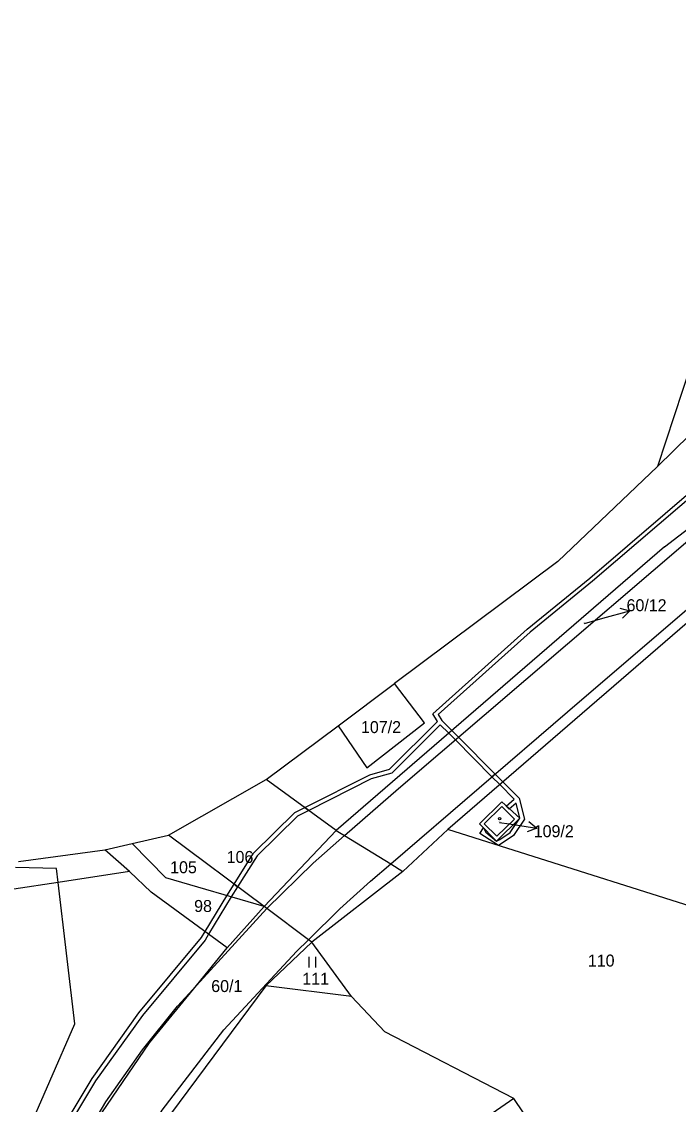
# Model space of a CAD drawing. Extents: x -670359 to -668019, y -978807 to -976674.
# Drawn here: x -670157 to -670063.7, y -977284.7 to -977130.8 of the extents above; entities that cross this region are included whole.
import ezdxf

# ---------------------------------------------------------------- set-up
doc = ezdxf.new("R2010")
doc.units = 0
for name, color, linetype in [('Hranice kat_území', 7, 'Continuous'), ('Hranice parcel', 7, 'Continuous'), ('Parcelní čísla', 7, 'Continuous'), ('Vnitřní kresba', 7, 'Continuous'), ('Věcná břemena k části', 7, 'Continuous'), ('Značky budov', 7, 'Continuous'), ('Značky kultur', 7, 'Continuous')]:
    doc.layers.add(name, color=color, linetype=linetype)

msp = doc.modelspace()

# ---------------------------------------------------------------- linework, layer by layer
at = {"layer": 'Hranice kat_území'}
for points in [[(-670061.94, -977179.61), (-670066.67, -977194.02)], [(-670080.85, -977207.52), (-670066.67, -977194.02)], [(-670080.85, -977207.52), (-670104.05, -977224.88)], [(-670112.07, -977230.89), (-670104.05, -977224.88)], [(-670122.28, -977238.53), (-670112.07, -977230.89)], [(-670136.18, -977246.45), (-670122.28, -977238.53)], [(-670141.33, -977247.61), (-670136.18, -977246.45)], [(-670157.5, -977250.17), (-670145.24, -977248.5)], [(-670145.24, -977248.5), (-670141.33, -977247.61)]]:
    msp.add_lwpolyline(points, dxfattribs=at)
at = {"layer": 'Hranice parcel'}
for p, q in [((-670091.98, -977244.8), (-670088.78, -977241.68)), ((-670088.78, -977241.68), (-670086.24, -977244.04)), ((-670089.55, -977247.29), (-670091.98, -977244.8)), ((-670086.24, -977244.04), (-670089.55, -977247.29))]:
    msp.add_line(p, q, dxfattribs=at)
for points in [[(-670104.59, -977250.52), (-670079.48, -977228.88), (-670031.98, -977188.17), (-670021.47, -977179.22), (-669995.68, -977157.04), (-669989.1, -977151.37), (-669968.95, -977134.02), (-669965.11, -977130.8)], [(-670025, -977183.9), (-670096.49, -977245.64)], [(-670057.51, -977185.02), (-670066.67, -977194.02)], [(-670111.14, -977246.5), (-670103.49, -977239.81), (-670043.26, -977188.26)], [(-670065.71, -977205.46), (-670043.26, -977188.26)], [(-670065.71, -977205.46), (-670112.33, -977245.77)], [(-670099.8, -977230.46), (-670104.05, -977224.88)], [(-670112.07, -977230.89), (-670108.01, -977236.86)], [(-670108.01, -977236.86), (-670099.8, -977230.46)], [(-670112.33, -977245.77), (-670122.28, -977238.53)], [(-670122.59, -977256.59), (-670136.18, -977246.45)], [(-670122.59, -977256.59), (-670112.33, -977245.77)], [(-670122.22, -977256.86), (-670115.62, -977250.42), (-670111.14, -977246.5)], [(-670096.49, -977245.64), (-670102.85, -977251.59)], [(-670050.66, -977260.11), (-670096.49, -977245.64)], [(-670141.7, -977251.6), (-670145.24, -977248.5)], [(-670136.55, -977252.48), (-670141.33, -977247.61)], [(-670141.7, -977251.6), (-670151.87, -977253.14)], [(-670138.64, -977254.54), (-670141.7, -977251.6)], [(-670116.3, -977261.29), (-670111.81, -977256.89), (-670107.46, -977252.99), (-670104.59, -977250.52)], [(-670102.85, -977251.59), (-670115.81, -977261.66)], [(-670151.87, -977253.14), (-670158.17, -977254.09)], [(-670122.59, -977256.59), (-670136.55, -977252.48)], [(-670127.82, -977262.45), (-670138.64, -977254.54)], [(-670132.18, -977267.78), (-670122.22, -977256.86)], [(-670127.82, -977262.45), (-670122.59, -977256.59)], [(-670206.03, -977490.9), (-670201.37, -977472.26), (-670196.78, -977453.99), (-670188.6, -977424.41), (-670168.29, -977357.64), (-670162.97, -977342.22), (-670144.87, -977298.55), (-670137.06, -977285.54), (-670128.3, -977274.09), (-670118, -977262.95), (-670116.3, -977261.29)], [(-670132.18, -977267.78), (-670127.82, -977262.45)], [(-670115.81, -977261.66), (-670122.33, -977267.85)], [(-670110.18, -977269.38), (-670115.81, -977261.66)], [(-670155.78, -977304.6), (-670149.86, -977292.46), (-670145.08, -977284.34), (-670139.87, -977276.96), (-670134.89, -977270.75), (-670132.18, -977267.78)], [(-670138.88, -977275.97), (-670132.18, -977267.78)], [(-670122.33, -977267.85), (-670138.33, -977289.41)], [(-670110.18, -977269.38), (-670122.33, -977267.85)], [(-670105.42, -977274.37), (-670110.18, -977269.38)], [(-670087.08, -977283.85), (-670105.42, -977274.37)], [(-670145.67, -977285.92), (-670138.88, -977275.97)], [(-670087.08, -977283.85), (-670131.79, -977314.81)], [(-670084.43, -977287.79), (-670087.08, -977283.85)]]:
    msp.add_lwpolyline(points, dxfattribs=at)
at = {"layer": 'Parcelní čísla'}
for p, q in [((-670072.05, -977214.16), (-670070.6, -977214.54)), ((-670077.05, -977216.33), (-670074.45, -977215.61)), ((-670089.12, -977244.63), (-670087.77, -977244.83)), ((-670084.99, -977244.5), (-670083.82, -977245.44))]:
    msp.add_line(p, q, dxfattribs=at)
for points in [[(-670074.45, -977215.61), (-670070.6, -977214.54), (-670071.65, -977215.61)], [(-670087.77, -977244.83), (-670083.82, -977245.44), (-670085.21, -977245.98)]]:
    msp.add_lwpolyline(points, dxfattribs=at)
at = {"layer": 'Vnitřní kresba'}
for p, q in [((-670091.31, -977244.8), (-670088.79, -977242.37)), ((-670088.79, -977242.37), (-670087.01, -977244.14)), ((-670089.52, -977246.59), (-670091.31, -977244.8)), ((-670087.01, -977244.14), (-670089.52, -977246.59))]:
    msp.add_line(p, q, dxfattribs=at)
for points in [[(-670112.33, -977245.77), (-670111.14, -977246.5)], [(-670111.14, -977246.5), (-670104.59, -977250.52)], [(-670152.1, -977251.15), (-670157.9, -977251.05)], [(-670151.87, -977253.14), (-670152.1, -977251.15)], [(-670104.59, -977250.52), (-670102.85, -977251.59)], [(-670149.5, -977273.26), (-670151.87, -977253.14)], [(-670122.22, -977256.86), (-670122.59, -977256.59)], [(-670116.3, -977261.29), (-670122.22, -977256.86)], [(-670115.81, -977261.66), (-670116.3, -977261.29)], [(-670156.58, -977289.53), (-670149.5, -977273.26)]]:
    msp.add_lwpolyline(points, dxfattribs=at)
at = {"layer": 'Věcná břemena k části'}
for p, q in [((-670076.28, -977209.88), (-670054.39, -977191.06)), ((-670053.99, -977191.52), (-670075.9, -977210.34)), ((-670085.18, -977217.13), (-670076.28, -977209.88)), ((-670075.9, -977210.34), (-670084.78, -977217.59)), ((-670098.62, -977229.19), (-670085.18, -977217.13)), ((-670084.78, -977217.59), (-670097.84, -977229.29)), ((-670097.94, -977230.27), (-670098.62, -977229.19)), ((-670097.84, -977229.29), (-670097.32, -977230.12)), ((-670097.32, -977230.12), (-670095.9, -977231.56)), ((-670104.77, -977237.07), (-670097.94, -977230.27)), ((-670097.56, -977230.73), (-670104.45, -977237.61)), ((-670096.35, -977231.95), (-670097.56, -977230.73)), ((-670116.8, -977242.52), (-670107.57, -977237.86)), ((-670107.57, -977237.86), (-670104.77, -977237.07)), ((-670104.45, -977237.61), (-670107.35, -977238.42)), ((-670107.35, -977238.42), (-670116.25, -977242.91))]:
    msp.add_line(p, q, dxfattribs=at)
for points in [[(-670095.9, -977231.56), (-670094.96, -977232.51), (-670095.41, -977232.9), (-670096.35, -977231.95), (-670095.9, -977231.56)], [(-670095.9, -977231.56), (-670096.35, -977231.95)], [(-670095.41, -977232.9), (-670094.96, -977232.51), (-670089.76, -977237.74), (-670090.21, -977238.13), (-670095.41, -977232.9)], [(-670089.76, -977237.74), (-670088.64, -977238.86), (-670086.34, -977241.18), (-670085.6, -977244.16), (-670087.16, -977246.46), (-670089.03, -977247.76), (-670089.26, -977247.92), (-670091.95, -977246.22), (-670091.4, -977245.39), (-670091.09, -977246), (-670089.55, -977247.29), (-670089.07, -977247.06), (-670087.6, -977246.04), (-670086.24, -977244.04), (-670086.78, -977241.87), (-670087.77, -977242.72), (-670088.19, -977242.29), (-670087.05, -977241.31), (-670089.1, -977239.25), (-670090.21, -977238.13), (-670089.76, -977237.74)], [(-670126.84, -977253.42), (-670124.07, -977249.01), (-670118.2, -977243.22), (-670116.8, -977242.52), (-670116.25, -977242.91), (-670117.84, -977243.72), (-670123.59, -977249.39), (-670126.36, -977253.78)], [(-670116.25, -977242.91), (-670116.8, -977242.52)], [(-670152.64, -977290.41), (-670147.04, -977281.03), (-670140.37, -977271.71), (-670131.47, -977261), (-670130.96, -977260.15), (-670127.86, -977255.04), (-670126.84, -977253.42), (-670126.36, -977253.78), (-670127.26, -977255.21), (-670130.48, -977260.51), (-670130.97, -977261.34), (-670139.89, -977272.07), (-670146.54, -977281.35), (-670152.12, -977290.69)], [(-670126.36, -977253.78), (-670126.84, -977253.42)]]:
    msp.add_lwpolyline(points, dxfattribs=at)
at = {"layer": 'Značky budov'}
msp.add_circle((-670089.12, -977244.1), 0.175, dxfattribs=at)
at = {"layer": 'Značky kultur'}
for p, q in [((-670116.22, -977263.74), (-670116.22, -977265.24)), ((-670115.22, -977265.24), (-670115.22, -977263.74))]:
    msp.add_line(p, q, dxfattribs=at)
msp.add_circle((-670089.12, -977244.1), 0.175, dxfattribs=at)

# ---------------------------------------------------------------- texts
at = {"layer": 'Parcelní čísla'}
for s, height, p in [('60/12', 1.7, (-670071.08, -977214.6)), ('60/12', 0.1, (-670077.24, -977216.33)), ('107/2', 1.7, (-670108.82, -977231.92)), ('109/2', 0.1, (-670089.31, -977244.63)), ('109/2', 1.7, (-670084.27, -977246.72)), ('105', 1.7, (-670135.94, -977251.84)), ('106', 1.7, (-670127.91, -977250.38)), ('98', 1.7, (-670132.53, -977257.35)), ('110', 1.7, (-670076.58, -977265.11)), ('60/1', 1.7, (-670130.1, -977268.73)), ('111', 1.7, (-670117.16, -977267.7))]:
    msp.add_text(s, height=height, dxfattribs=at).set_placement(p)

doc.saveas('drawing.dxf')
